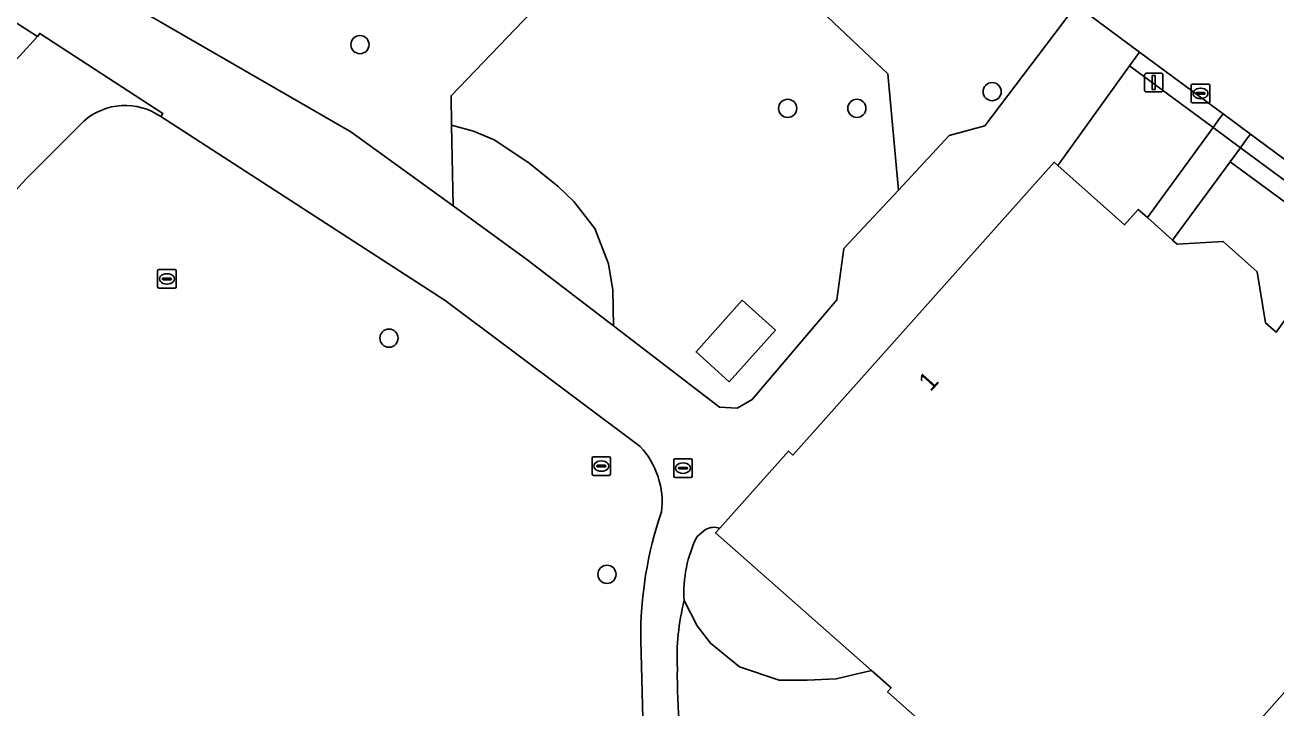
# Model space of a CAD drawing. Extents: x 161402 to 161933, y 381647 to 382315.
# Drawn here: x 161620 to 161687.4, y 382075.9 to 382112.6 of the extents above; entities that cross this region are included whole.
import ezdxf

# ---------------------------------------------------------------- set-up
doc = ezdxf.new("R2010")
doc.units = 0
for name, color, linetype in [('IMGEO_Boom', 7, 'Continuous'), ('IMGEO_Brandkraan', 7, 'Continuous'), ('IMGEO_Groenvoorziening', 7, 'Continuous'), ('IMGEO_Kolk', 7, 'Continuous'), ('IMGEO_Lichtmast', 7, 'Continuous'), ('IMGEO_Pand', 7, 'Continuous'), ('IMGEO_Pand_nummerreeks', 7, 'Continuous'), ('IMGEO_Parkeervlak_open', 7, 'Continuous'), ('IMGEO_Rijbaan_lokaal_gesloten', 7, 'Continuous'), ('IMGEO_Rioolput', 7, 'Continuous'), ('IMGEO_Voetpad_gesloten', 7, 'Continuous'), ('IMGEO_Voetpad_open', 7, 'Continuous')]:
    doc.layers.add(name, color=color, linetype=linetype)

msp = doc.modelspace()

# ---------------------------------------------------------------- linework, layer by layer
at = {"layer": 'IMGEO_Boom'}
for centre in [(161638.067, 382111.59), (161672.082, 382109.06), (161661.081, 382108.158), (161664.806, 382108.159), (161639.627, 382095.8), (161651.358, 382083.094)]:
    msp.add_circle(centre, 0.489, dxfattribs=at)
at = {"layer": 'IMGEO_Brandkraan'}
for p, q in [((161650.555, 382088.493), (161650.555, 382089.345)), ((161650.63, 382089.419), (161651.482, 382089.419)), ((161651.043, 382089.199), (161651.068, 382089.199)), ((161651.556, 382089.345), (161651.556, 382088.493)), ((161650.814, 382088.913), (161650.814, 382088.925)), ((161651.252, 382088.876), (161650.854, 382088.876)), ((161650.857, 382088.962), (161651.255, 382088.962)), ((161651.066, 382088.639), (161651.041, 382088.639)), ((161651.298, 382088.925), (161651.298, 382088.913)), ((161651.482, 382088.419), (161650.63, 382088.419))]:
    msp.add_line(p, q, dxfattribs=at)
for points in [[(161650.555, 382088.493), (161650.555, 382089.345)], [(161650.63, 382089.419), (161651.482, 382089.419)], [(161651.556, 382089.345), (161651.556, 382088.493)], [(161651.482, 382088.419), (161650.63, 382088.419)]]:
    msp.add_lwpolyline(points, dxfattribs=at)
for centre, radius, start, end in [((161650.632, 382089.343), 0.0765, 91.55205, 178.44795), ((161650.632, 382089.343), 0.0765, 91.55205, 178.44795), ((161651.48, 382089.343), 0.0765, 1.55205, 88.44795), ((161651.48, 382089.343), 0.0765, 1.55205, 88.44795), ((161650.632, 382088.495), 0.0765, 181.55205, 268.44795), ((161650.632, 382088.495), 0.0765, 181.55205, 268.44795), ((161650.854, 382088.922), 0.0403, 85.87752, 175.75265), ((161650.851, 382088.912), 0.0366, 178.93798, 274.71019), ((161651.255, 382088.919), 0.043, 264.86636, 352.45326), ((161651.259, 382088.924), 0.0386, 1.73085, 96.63898), ((161651.48, 382088.495), 0.0765, 271.55205, 358.44795), ((161651.48, 382088.495), 0.0765, 271.55205, 358.44795)]:
    msp.add_arc(centre, radius, start, end, dxfattribs=at)
for centre, major_axis, ratio, start_param, end_param in [((161651.042, 382088.919), (-0.387, 0.002), 0.722429, 4.712389, 7.853982), ((161651.067, 382088.919), (-0.39, 0.002), 0.717154, 1.570796, 4.712389)]:
    msp.add_ellipse(centre, major_axis=major_axis, ratio=ratio, start_param=start_param, end_param=end_param, dxfattribs=at)
at = {"layer": 'IMGEO_Groenvoorziening'}
for points in [[(161654.378, 382125.902), (161650.606, 382123.843), (161651.002, 382123.392), (161657.312, 382117.637), (161663.216, 382113.089), (161666.474, 382110.021), (161667.036, 382103.767), (161669.764, 382106.692), (161671.685, 382107.22), (161675.409, 382112.109), (161676.612, 382113.709)], [(161647.707, 382113.768), (161642.974, 382108.838), (161643.001, 382107.249), (161644.181, 382106.93), (161645.286, 382106.461), (161647.162, 382105.221), (161648.736, 382103.948), (161649.573, 382103.144), (161650.712, 382101.703), (161651.448, 382099.793), (161651.683, 382098.386), (161651.716, 382096.456), (161657.422, 382092.083), (161658.357, 382092.042), (161659.175, 382092.497), (161663.724, 382097.855), (161664.11, 382100.63), (161667.036, 382103.767), (161666.474, 382110.021), (161663.216, 382113.089)], [(161623.227, 382107.487), (161620.087, 382104.351), (161617.101, 382101.069), (161613.116, 382096.259), (161609.394, 382091.242), (161601.21, 382078.942), (161605.875, 382074.355), (161609.485, 382066.301)], [(161653.149, 382089.979), (161642.659, 382097.82), (161627.348, 382107.722)], [(161655.512, 382081.683), (161656.21, 382080.326), (161656.923, 382079.398), (161658.492, 382078.114), (161660.631, 382077.4), (161662.128, 382077.4), (161663.697, 382077.472), (161665.585, 382077.928), (161657.205, 382085.324), (161657.433, 382085.58)], [(161656.656, 382085.506), (161656.206, 382085.136)], [(161653.34, 382073.273), (161653.177, 382079.541)]]:
    msp.add_lwpolyline(points, dxfattribs=at)
for points in [[(161643.655, 382118.417), (161641.43, 382116.651), (161639.659, 382118.883), (161641.884, 382120.65), (161639.936, 382122.778), (161637.456, 382125.144), (161631.524, 382119.109), (161626.292, 382113.405), (161637.576, 382106.904), (161643.075, 382102.915), (161643.001, 382107.249), (161642.974, 382108.838), (161647.707, 382113.768)], [(161608.435, 382119.953), (161574.421, 382075.333), (161571.745, 382071.279), (161570.174, 382069.09), (161570.085, 382068.306), (161570.428, 382067.596), (161581.666, 382057.913), (161582.301, 382057.757), (161582.818, 382058.156), (161592.764, 382074.245), (161598.47, 382083.033), (161608.254, 382097.285), (161612.452, 382102.646), (161616.48, 382107.434), (161620.728, 382112.027), (161610.839, 382118.38)], [(161648.736, 382103.948), (161647.162, 382105.221), (161645.286, 382106.461), (161644.181, 382106.93), (161643.001, 382107.249), (161643.075, 382102.915), (161647.044, 382100.036), (161651.716, 382096.456), (161651.683, 382098.386), (161651.448, 382099.793), (161650.712, 382101.703), (161649.573, 382103.144)], [(161658.637, 382097.837), (161660.426, 382096.233), (161657.939, 382093.459), (161656.15, 382095.062)]]:
    msp.add_lwpolyline(points, close=True, dxfattribs=at)
for centre, radius, start, end in [((161625.44, 382104.939), 3.375, 55.56061, 130.96691), ((161649.901, 382086.975), 4.424, 353.19742, 42.76389), ((161673.716, 382079.766), 20.541, 161.00727, 180.62789), ((161662.284, 382082.118), 6.786, 153.59413, 183.67754), ((161657.132, 382084.627), 0.999, 72.45264, 118.42802)]:
    msp.add_arc(centre, radius, start, end, dxfattribs=at)
at = {"layer": 'IMGEO_Kolk'}
for p, q in [((161682.793, 382108.535), (161682.793, 382109.387)), ((161682.868, 382109.461), (161683.72, 382109.461)), ((161683.794, 382109.387), (161683.794, 382108.535)), ((161683.052, 382108.955), (161683.052, 382108.967)), ((161683.49, 382108.918), (161683.092, 382108.918)), ((161683.095, 382109.004), (161683.493, 382109.004)), ((161683.304, 382108.681), (161683.279, 382108.681)), ((161683.281, 382109.241), (161683.306, 382109.241)), ((161683.536, 382108.967), (161683.536, 382108.955)), ((161683.72, 382108.461), (161682.868, 382108.461)), ((161654.949, 382088.382), (161654.949, 382089.234)), ((161655.024, 382089.308), (161655.876, 382089.308)), ((161655.95, 382089.234), (161655.95, 382088.382)), ((161655.208, 382088.802), (161655.208, 382088.814)), ((161655.646, 382088.765), (161655.248, 382088.765)), ((161655.251, 382088.851), (161655.649, 382088.851)), ((161655.46, 382088.528), (161655.435, 382088.528)), ((161655.437, 382089.088), (161655.462, 382089.088)), ((161655.692, 382088.814), (161655.692, 382088.802)), ((161655.876, 382088.308), (161655.024, 382088.308))]:
    msp.add_line(p, q, dxfattribs=at)
for points in [[(161682.793, 382108.535), (161682.793, 382109.387)], [(161682.868, 382109.461), (161683.72, 382109.461)], [(161683.794, 382109.387), (161683.794, 382108.535)], [(161683.72, 382108.461), (161682.868, 382108.461)], [(161654.949, 382088.382), (161654.949, 382089.234)], [(161655.024, 382089.308), (161655.876, 382089.308)], [(161655.95, 382089.234), (161655.95, 382088.382)], [(161655.876, 382088.308), (161655.024, 382088.308)]]:
    msp.add_lwpolyline(points, dxfattribs=at)
for centre, radius, start, end in [((161682.87, 382109.385), 0.0765, 91.55205, 178.44795), ((161682.87, 382109.385), 0.0765, 91.55205, 178.44795), ((161683.718, 382109.385), 0.0765, 1.55205, 88.44795), ((161683.718, 382109.385), 0.0765, 1.55205, 88.44795), ((161683.092, 382108.964), 0.0403, 85.87752, 175.75265), ((161683.089, 382108.954), 0.0366, 178.93798, 274.71019), ((161683.493, 382108.961), 0.043, 264.86636, 352.45326), ((161683.497, 382108.966), 0.0386, 1.73085, 96.63898), ((161682.87, 382108.537), 0.0765, 181.55205, 268.44795), ((161682.87, 382108.537), 0.0765, 181.55205, 268.44795), ((161683.718, 382108.537), 0.0765, 271.55205, 358.44795), ((161683.718, 382108.537), 0.0765, 271.55205, 358.44795), ((161655.026, 382089.232), 0.0765, 91.55205, 178.44795), ((161655.026, 382089.232), 0.0765, 91.55205, 178.44795), ((161655.874, 382089.232), 0.0765, 1.55205, 88.44795), ((161655.874, 382089.232), 0.0765, 1.55205, 88.44795), ((161655.248, 382088.811), 0.0403, 85.87752, 175.75265), ((161655.245, 382088.801), 0.0366, 178.93798, 274.71019), ((161655.649, 382088.808), 0.043, 264.86636, 352.45326), ((161655.653, 382088.813), 0.0386, 1.73085, 96.63898), ((161655.026, 382088.384), 0.0765, 181.55205, 268.44795), ((161655.026, 382088.384), 0.0765, 181.55205, 268.44795), ((161655.874, 382088.384), 0.0765, 271.55205, 358.44795), ((161655.874, 382088.384), 0.0765, 271.55205, 358.44795)]:
    msp.add_arc(centre, radius, start, end, dxfattribs=at)
for centre, major_axis, ratio, start_param, end_param in [((161683.28, 382108.961), (-0.387, 0.002), 0.722429, 4.712389, 7.853982), ((161683.305, 382108.961), (-0.39, 0.002), 0.717154, 1.570796, 4.712389), ((161655.436, 382088.808), (-0.387, 0.002), 0.722429, 4.712389, 7.853982), ((161655.461, 382088.808), (-0.39, 0.002), 0.717154, 1.570796, 4.712389)]:
    msp.add_ellipse(centre, major_axis=major_axis, ratio=ratio, start_param=start_param, end_param=end_param, dxfattribs=at)
at = {"layer": 'IMGEO_Lichtmast'}
for p, q in [((161680.38, 382110.048), (161681.17, 382110.048)), ((161681.17, 382110.048), (161680.38, 382110.048)), ((161680.28, 382109.148), (161680.28, 382109.948)), ((161680.28, 382109.948), (161680.28, 382109.148)), ((161681.27, 382109.948), (161681.27, 382109.148)), ((161681.27, 382109.148), (161681.27, 382109.948)), ((161681.17, 382109.048), (161680.38, 382109.048)), ((161680.38, 382109.048), (161681.17, 382109.048))]:
    msp.add_line(p, q, dxfattribs=at)
msp.add_lwpolyline([(161680.7, 382109.923), (161680.85, 382109.923), (161680.85, 382109.173), (161680.7, 382109.173), (161680.7, 382109.923)], dxfattribs=at)
for centre, start, end in [((161680.38, 382109.948), 90, 180), ((161680.38, 382109.948), 90, 180), ((161681.17, 382109.948), 0, 90), ((161681.17, 382109.948), 360, 90), ((161680.38, 382109.148), 180, 270), ((161680.38, 382109.148), 180, 270), ((161681.17, 382109.148), 270, 0), ((161681.17, 382109.148), 270, 0)]:
    msp.add_arc(centre, 0.1, start, end, dxfattribs=at)
at = {"layer": 'IMGEO_Pand'}
for points in [[(161687.358, 382096.12), (161686.797, 382096.621), (161686.348, 382099.358), (161684.51, 382101.001), (161682.033, 382100.863), (161681.793, 382101.078), (161680.438, 382102.289), (161679.947, 382102.728), (161679.199, 382101.892), (161675.625, 382105.087), (161675.428, 382105.263), (161661.355, 382089.507), (161661.133, 382089.726), (161657.433, 382085.58), (161657.205, 382085.324), (161665.585, 382077.928), (161666.644, 382076.993), (161666.455, 382076.78), (161670.499, 382073.171)], [(161681.866, 382070.054), (161688.839, 382077.902)]]:
    msp.add_lwpolyline(points, dxfattribs=at)
msp.add_lwpolyline([(161657.939, 382093.459), (161660.426, 382096.233), (161658.637, 382097.837), (161656.15, 382095.062)], close=True, dxfattribs=at)
at = {"layer": 'IMGEO_Parkeervlak_open'}
msp.add_arc((161779.754, 382195.552), 121.198, 210.75283, 225.67105, dxfattribs=at)
at = {"layer": 'IMGEO_Rijbaan_lokaal_gesloten'}
msp.add_lwpolyline([(161662.46, 382124.887), (161669.643, 382118.964), (161671.067, 382117.859), (161672.475, 382116.767), (161674.249, 382115.428), (161675.855, 382114.229), (161676.612, 382113.709), (161680.02, 382111.186), (161683.217, 382108.819), (161684.511, 382107.862), (161685.976, 382106.779), (161691.909, 382102.395), (161692.031, 382102.304), (161693.377, 382101.307), (161695.005, 382100.101), (161703.278, 382093.969), (161714.444, 382085.706)], dxfattribs=at)
msp.add_arc((161779.754, 382195.552), 121.198, 210.75283, 225.67105, dxfattribs=at)
at = {"layer": 'IMGEO_Rioolput'}
for p, q in [((161627.18, 382098.562), (161627.18, 382099.414)), ((161627.255, 382099.488), (161628.107, 382099.488)), ((161627.668, 382099.268), (161627.693, 382099.268)), ((161628.181, 382099.414), (161628.181, 382098.562)), ((161627.439, 382098.982), (161627.439, 382098.994)), ((161627.877, 382098.945), (161627.479, 382098.945)), ((161627.482, 382099.031), (161627.88, 382099.031)), ((161627.691, 382098.708), (161627.666, 382098.708)), ((161627.923, 382098.994), (161627.923, 382098.982)), ((161628.107, 382098.488), (161627.255, 382098.488))]:
    msp.add_line(p, q, dxfattribs=at)
for points in [[(161627.18, 382098.562), (161627.18, 382099.414)], [(161627.255, 382099.488), (161628.107, 382099.488)], [(161628.181, 382099.414), (161628.181, 382098.562)], [(161628.107, 382098.488), (161627.255, 382098.488)]]:
    msp.add_lwpolyline(points, dxfattribs=at)
for centre, radius, start, end in [((161627.257, 382099.412), 0.0765, 91.55205, 178.44795), ((161627.257, 382099.412), 0.0765, 91.55205, 178.44795), ((161628.105, 382099.412), 0.0765, 1.55205, 88.44795), ((161628.105, 382099.412), 0.0765, 1.55205, 88.44795), ((161627.479, 382098.991), 0.0403, 85.87752, 175.75265), ((161627.476, 382098.981), 0.0366, 178.93798, 274.71019), ((161627.88, 382098.988), 0.043, 264.86636, 352.45326), ((161627.884, 382098.993), 0.0386, 1.73085, 96.63898), ((161627.257, 382098.564), 0.0765, 181.55205, 268.44795), ((161627.257, 382098.564), 0.0765, 181.55205, 268.44795), ((161628.105, 382098.564), 0.0765, 271.55205, 358.44795), ((161628.105, 382098.564), 0.0765, 271.55205, 358.44795)]:
    msp.add_arc(centre, radius, start, end, dxfattribs=at)
for centre, major_axis, ratio, start_param, end_param in [((161627.667, 382098.988), (-0.387, 0.002), 0.722429, 4.712389, 7.853982), ((161627.692, 382098.988), (-0.39, 0.002), 0.717154, 1.570796, 4.712389)]:
    msp.add_ellipse(centre, major_axis=major_axis, ratio=ratio, start_param=start_param, end_param=end_param, dxfattribs=at)
at = {"layer": 'IMGEO_Voetpad_gesloten'}
for points in [[(161651.716, 382096.456), (161647.044, 382100.036), (161643.075, 382102.915), (161637.576, 382106.904), (161626.292, 382113.405), (161623.482, 382114.851), (161616.517, 382119.3), (161613.002, 382121.603), (161610.839, 382118.38), (161620.728, 382112.027), (161620.837, 382112.195), (161627.457, 382107.89), (161627.348, 382107.722), (161642.659, 382097.82), (161653.149, 382089.979)], [(161657.433, 382085.58), (161661.133, 382089.726), (161661.355, 382089.507), (161675.428, 382105.263), (161675.625, 382105.087), (161679.472, 382110.441), (161680.02, 382111.186), (161676.612, 382113.709), (161675.409, 382112.109), (161671.685, 382107.22), (161669.764, 382106.692), (161667.036, 382103.767), (161664.11, 382100.63), (161663.724, 382097.855), (161659.175, 382092.497), (161658.357, 382092.042), (161657.422, 382092.083), (161651.716, 382096.456)], [(161627.348, 382107.722), (161627.457, 382107.89), (161620.837, 382112.195), (161620.728, 382112.027), (161616.48, 382107.434), (161612.452, 382102.646), (161608.254, 382097.285), (161598.47, 382083.033), (161592.764, 382074.245), (161582.818, 382058.156), (161579.545, 382052.829), (161579.356, 382052.267), (161574.693, 382046.208), (161566.397, 382035.429), (161567.213, 382029.55), (161574.039, 382037.028), (161581.425, 382047.268), (161587.35, 382055.783), (161588.122, 382057.524), (161592.51, 382064.912), (161594.145, 382067.66)], [(161594.145, 382067.66), (161601.21, 382078.942), (161609.394, 382091.242), (161613.116, 382096.259), (161617.101, 382101.069), (161620.087, 382104.351), (161623.227, 382107.487)], [(161656.206, 382085.136), (161656.656, 382085.506)], [(161653.177, 382079.541), (161653.34, 382073.273)]]:
    msp.add_lwpolyline(points, dxfattribs=at)
for centre, radius, start, end in [((161625.44, 382104.939), 3.375, 55.56061, 130.96691), ((161649.901, 382086.975), 4.424, 353.19742, 42.76389), ((161673.716, 382079.766), 20.541, 161.00727, 180.62789), ((161662.284, 382082.118), 6.786, 153.59413, 183.67754), ((161657.132, 382084.627), 0.999, 72.45264, 118.42802), ((161667.438, 382078.65), 12.306, 165.73144, 182.88775), ((161685.375, 382077.568), 30.231, 179.12433, 191.36272)]:
    msp.add_arc(centre, radius, start, end, dxfattribs=at)
at = {"layer": 'IMGEO_Voetpad_open'}
for points in [[(161680.02, 382111.186), (161679.472, 382110.441), (161683.974, 382107.132), (161684.324, 382107.612), (161684.511, 382107.862), (161683.217, 382108.819)], [(161683.974, 382107.132), (161679.472, 382110.441), (161675.625, 382105.087), (161679.199, 382101.892), (161679.947, 382102.728), (161680.438, 382102.289)], [(161684.511, 382107.862), (161684.324, 382107.612), (161683.974, 382107.132), (161685.443, 382106.045), (161685.776, 382106.498), (161685.976, 382106.779)], [(161685.443, 382106.045), (161683.974, 382107.132), (161680.438, 382102.289), (161681.793, 382101.078), (161684.886, 382105.287)], [(161685.976, 382106.779), (161685.776, 382106.498), (161685.443, 382106.045), (161691.375, 382101.657), (161691.737, 382102.156), (161691.909, 382102.395)], [(161684.886, 382105.287), (161686.844, 382103.846), (161688.809, 382102.4), (161690.833, 382100.91), (161691.375, 382101.657), (161685.443, 382106.045)], [(161690.833, 382100.91), (161688.809, 382102.4), (161686.844, 382103.846), (161684.886, 382105.287), (161681.793, 382101.078), (161682.033, 382100.863), (161684.51, 382101.001), (161686.348, 382099.358), (161686.797, 382096.621), (161687.358, 382096.12)]]:
    msp.add_lwpolyline(points, close=True, dxfattribs=at)
for points in [[(161670.499, 382073.171), (161666.455, 382076.78), (161666.644, 382076.993), (161665.585, 382077.928), (161663.697, 382077.472), (161662.128, 382077.4), (161660.631, 382077.4), (161658.492, 382078.114), (161656.923, 382079.398), (161656.21, 382080.326), (161655.512, 382081.683)], [(161688.344, 382073.304), (161690.918, 382075.927), (161693.628, 382078.779), (161691.374, 382080.754), (161688.839, 382077.902), (161681.866, 382070.054)]]:
    msp.add_lwpolyline(points, dxfattribs=at)
for centre, radius, start, end in [((161667.438, 382078.65), 12.306, 165.73144, 182.88775), ((161685.375, 382077.568), 30.231, 179.12433, 191.36272)]:
    msp.add_arc(centre, radius, start, end, dxfattribs=at)

# ---------------------------------------------------------------- texts
at = {"layer": 'IMGEO_Pand_nummerreeks'}
msp.add_text('1', height=1, rotation=48.2293, dxfattribs=at).set_placement((161668.771, 382092.887))

doc.saveas('drawing.dxf')
